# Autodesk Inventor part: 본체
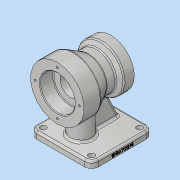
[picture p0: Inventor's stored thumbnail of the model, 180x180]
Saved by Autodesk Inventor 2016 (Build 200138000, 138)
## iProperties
Created: 2019-01
Part Number: 본체
Material: 알루미늄 6061
Document SubType Name: Modeling
Designer: Administrator
Density: 2.7 g/cm^3
Appearance: 알루미늄 - 평지
Mass: 898.816 g
Surface Area: 600.964 cm^2
Volume: 332.895 cm^3
Author: Administrator
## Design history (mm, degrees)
sketch "스케치1"
  geometry: L1 (46, -46)-(-46, -46); L2 (-46, -46)-(-46, 46); L3 (-46, 46)-(46, 46); L4 (46, 46)-(46, -46); L5 (46, -46)-(-46, 46); L6 (-46, -46)-(46, 46); 1 further point
  constraints: 12 end point, 2 midpoint, 2 parallel, 1 horizontal, 1 perpendicular
  dimensions: "d0" = 92 distance of L2.end L3.end; "d1" = 92 distance of L1.end L2.end
extrude "돌출1" new body sketch "스케치1" distance "d2" = 10; taper "d3" = 0 deg
fillet "모깎기1" dims "d4" = 10
fillet "모깎기2" dims "d5" = 10
sketch "스케치2"
  geometry: A1 r 10 centre (-36, -36) between (-46, -36) and (-36, -46) reference; 2 further points
  constraints: 1 coincident
hole "구멍1" sketch "스케치2" at (-36, -36) diameter "d6" = 9; stored, may be unused: countersink angle "d10" = 90 deg, drill point angle "d12" = 118 deg; dims "d7" = 6, "d8" = 4, "d9" = 2, "d11" = 8
sketch "스케치3"
  geometry: L1 (0, 0)-(0, 80); L2 (-51, 80)-(29, 80); L3 (-51, 80)-(-51, 120); L4 (-51, 120)-(-26, 120); L5 (-26, 120)-(-5.215, 108); L6 (-5.215, 108)-(8.126, 108); L7 (8.126, 108)-(14, 115); L8 (14, 115)-(29, 115); L9 (29, 115)-(29, 80); L10 (-46, 10)-(-46, 0) reference
  constraints: 18 end point, 2 parallel, 2 perpendicular, 2 vertical, 1 horizontal, 1 horizontal alignment
  dimensions: "d13" = 80 distance of L1.start L1.end; "d14" = 80 distance of L2.start L2.end; "d15" = 25 distance of L3.end L4.end; "d16" = 15 distance of L7.end L8.end; "d17" = 50 deg angle of L6 L7; "d18" = 30 deg angle of L6 L5; "d20" = 40 distance of L2.start L3.end; "d21" = 35 distance of L8.end L2.end; "d22" = 56 diameter of L6 L2; "d23" = 5 distance between parallel lines of L3 L10
revolve "회전1" sketch "스케치3" stored, may be unused: angle "d24" = 90 deg
sketch "스케치4"
  geometry: L1 (-51, 40)-(-51, 120) reference; L2 (-51, 80)-(29, 80); L3 (29, 45)-(29, 115) reference; L4 (29, 80)-(29, 100); L5 (29, 100)-(12, 100); L6 (12, 100)-(12, 96); L7 (12, 96)-(-31, 96); L8 (-31, 96)-(-31, 106); L9 (-31, 106)-(-51, 106); L10 (-51, 106)-(-51, 80); 1 further point
  constraints: 16 end point, 5 perpendicular, 2 midpoint, 2 point on line, 1 horizontal
  dimensions: "d25" = 20 distance of L8.end L9.end; "d26" = 17 distance of L4.end L5.end; "d27" = 52 diameter of L9 L2; "d28" = 32 diameter of L7 L2; "d29" = 40 diameter of L5 L2
revolve "회전2" sketch "스케치4" stored, may be unused: angle "d30" = 90 deg
sketch "스케치5"
  geometry: L1 (36, -46)-(-36, -46) reference; C1 r 16 at (0, -16); 1 further point
  constraints: 1 centre point, 1 vertical alignment
  dimensions: "d31" = 16 radius of C1; "d32" = 30 distance from line of L1 C1.centre
extrude "돌출2" join sketch "스케치5" stored distance "d33" = 10; taper "d34" = 0 deg
sketch "스케치7"
  geometry: L1 (36, 10)-(-36, 10) reference; L2 (0, 10)-(36, 10); L3 (36, 10)-(24.197, 35.312); L4 (36, 10)-(46, 10) reference; 1 further point
  constraints: 4 end point, 1 midpoint, 1 point on line
  dimensions: "d35" = 115 deg angle of L4 L3; "d36" = 10 distance of L4.end L2.end
feature "리브1" sketch "스케치7" dims "d37" = 1, "d38" = 10, "d39" = 0, "d40" = 0, "d41" = 1, "d42" = 1
sketch "스케치8"
  geometry: C1 r 20 at (0, 0) reference; C2 r 35 at (0, 0) reference; 2 further points
  constraints: 1 vertical alignment
  dimensions: "d43" = 27.5 distance of C1.centre point (0, -27.5)
hole "구멍2" sketch "스케치8" at (0, -27.5) diameter "d44" = 3.242; stored, may be unused: countersink angle "d48" = 90 deg, drill point angle "d50" = 118 deg; dims "d45" = 9, "d46" = 4, "d47" = 2, "d49" = 11
sketch "스케치9"
  geometry: C1 r 26 at (0, 0) reference; C2 r 40 at (0, 0) reference; 2 further points
  constraints: 1 vertical alignment
  dimensions: "d54" = 33 distance of point (0, 33) C1.centre
hole "구멍3" sketch "스케치9" at (0, 33) diameter "d55" = 3.242; stored, may be unused: countersink angle "d59" = 90 deg, drill point angle "d61" = 118 deg; dims "d56" = 9, "d57" = 4, "d58" = 2, "d60" = 11
sketch "스케치11"
  geometry: L1 (0, -10)-(10, -10) reference; L2 (10, 72)-(10, 0) reference; 2 further points
  constraints: 1 other
  dimensions: "d71" = 46 distance from line of L1 point (6, 36); "d72" = 4 distance from line of L2 point (6, 36)
fillet "모깎기3" dims "d73" = 3
fillet "모깎기4" dims "d74" = 3
fillet "모깎기5" dims "d75" = 0.6, "d76" = 1
chamfer "모따기1" distance "d77" = 1; stored, may be unused: second distance "d78" = 2, angle "d79" = 45 deg
chamfer "모따기2" distance "d80" = 1; stored, may be unused: second distance "d81" = 2, angle "d82" = 45 deg
fillet "모깎기6" dims "d83" = 3
fillet "모깎기7" dims "d84" = 3
feature "엠보싱1" dims "d0" = 92, "d1" = 92, "d85" = 0.5, "d86" = 0
feature "분할1"
node "솔리드1"
pattern_circular "원형 패턴1" dims angle "d52" = 360 deg
pattern_circular "원형 패턴2" dims angle "d63" = 360 deg
pattern_linear "직사각형 패턴1" dims "d67" = 72, "d70" = 72
node "투영된 루프1"
node "투영된 루프2"
